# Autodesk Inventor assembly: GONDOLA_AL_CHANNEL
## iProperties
Shininess: 64.0
Length Units: 11272
Angle Units: 11279
Time Units: 11290
Mass Units: 11286
Length Display Precision: 3
Angle Display Precision: 2
Compacted: True
Part Number: GONDOLA_AL_CHANNEL
Document SubType Name: Assembly
Created: 2004-08
Designer: John Blackburn
Manufacturer: Standard
Standards Organization: Custom
Density: 0.0
Volumn: 0.0
Area: 0.0
PropertySet Name: Model Information
Control State: 0
Master: False
Checked Out: False
Author: John Blackburn
